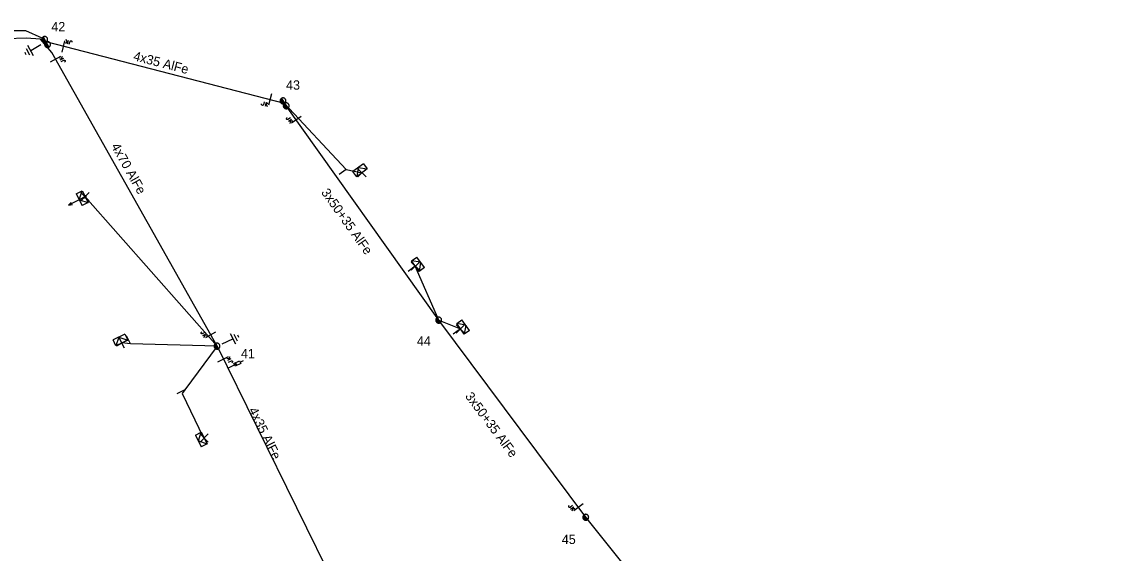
# Model space of a CAD drawing. Extents: x -536149 to -535465, y -1201639 to -1201298.
# Drawn here: x -535725.2 to -535608.3, y -1201357.9 to -1201301.1 of the extents above; entities that cross this region are included whole.
import ezdxf

# ---------------------------------------------------------------- set-up
doc = ezdxf.new("R2010")
doc.units = 0
for name, color, linetype in [('Vrstva 1', 7, 'Continuous'), ('Vrstva 13', 7, 'Continuous'), ('Vrstva 14', 7, 'Continuous'), ('Vrstva 15', 7, 'Continuous'), ('Vrstva 16', 7, 'Continuous'), ('Vrstva 18', 7, 'Continuous'), ('Vrstva 2', 7, 'Continuous'), ('Vrstva 31', 7, 'Continuous'), ('Vrstva 34', 7, 'Continuous'), ('Vrstva 5', 7, 'Continuous'), ('Vrstva 50', 7, 'Continuous'), ('Vrstva 54', 7, 'Continuous'), ('Vrstva 8', 7, 'Continuous'), ('Vrstva 9', 7, 'Continuous')]:
    doc.layers.add(name, color=color, linetype=linetype)

# ---------------------------------------------------------------- blocks, each defined once
blk = doc.blocks.new('NN440')
at = {"layer": 'Vrstva 2'}
for points in [[(0.63, 0), (0.63, 0.06), (0.62, 0.13), (0.6, 0.19), (0.58, 0.25), (0.55, 0.31), (0.51, 0.37), (0.47, 0.42), (0.42, 0.46), (0.37, 0.51), (0.32, 0.54), (0.26, 0.57), (0.2, 0.59), (0.13, 0.61), (0.07, 0.62), (0, 0.63), (-0.06, 0.62), (-0.13, 0.61), (-0.19, 0.59), (-0.26, 0.57), (-0.31, 0.54), (-0.37, 0.51), (-0.42, 0.46), (-0.47, 0.42), (-0.51, 0.37), (-0.54, 0.31), (-0.57, 0.25), (-0.6, 0.19), (-0.62, 0.13), (-0.63, 0.06), (-0.63, 0), (-0.63, -0.07), (-0.62, -0.14), (-0.6, -0.2), (-0.57, -0.26), (-0.54, -0.32), (-0.51, -0.37), (-0.47, -0.43), (-0.42, -0.47), (-0.37, -0.51), (-0.31, -0.55), (-0.26, -0.58), (-0.19, -0.6), (-0.13, -0.62), (-0.06, -0.63), (0, -0.63), (0.07, -0.63), (0.13, -0.62), (0.2, -0.6), (0.26, -0.58), (0.32, -0.55), (0.37, -0.51), (0.42, -0.47), (0.47, -0.43), (0.51, -0.37), (0.55, -0.32), (0.58, -0.26), (0.6, -0.2), (0.62, -0.14), (0.63, -0.07), (0.63, 0)], [(-0.63, 0), (0.63, 0)], [(-0.6, -0.18), (0.57, -0.18)], [(-0.51, -0.32), (0.5, -0.32)], [(-0.37, -0.47), (0.35, -0.47)]]:
    blk.add_lwpolyline(points, dxfattribs=at)
blk = doc.blocks.new('NN450')
at = {"layer": 'Vrstva 2'}
for points in [[(0, 0), (0, 0.07), (-0.01, 0.13), (-0.03, 0.19), (-0.05, 0.25), (-0.08, 0.31), (-0.12, 0.37), (-0.16, 0.42), (-0.21, 0.46), (-0.26, 0.51), (-0.31, 0.54), (-0.37, 0.57), (-0.43, 0.59), (-0.5, 0.61), (-0.56, 0.62), (-0.63, 0.62), (-0.69, 0.62), (-0.75, 0.61), (-0.82, 0.59), (-0.88, 0.57), (-0.94, 0.54), (-0.99, 0.51), (-1.04, 0.46), (-1.09, 0.42), (-1.13, 0.37), (-1.17, 0.31), (-1.2, 0.25), (-1.22, 0.19), (-1.24, 0.13), (-1.25, 0.07), (-1.25, 0), (-1.25, -0.07), (-1.24, -0.13), (-1.22, -0.19), (-1.2, -0.25), (-1.17, -0.31), (-1.13, -0.37), (-1.09, -0.42), (-1.04, -0.46), (-0.99, -0.51), (-0.94, -0.54), (-0.88, -0.57), (-0.82, -0.59), (-0.75, -0.61), (-0.69, -0.62), (-0.62, -0.63), (-0.56, -0.62), (-0.5, -0.61), (-0.43, -0.59), (-0.37, -0.57), (-0.31, -0.54), (-0.26, -0.51), (-0.21, -0.46), (-0.16, -0.42), (-0.12, -0.37), (-0.08, -0.31), (-0.05, -0.25), (-0.03, -0.19), (-0.01, -0.13), (0, -0.07), (0, 0)], [(1.25, 0), (1.25, 0.07), (1.24, 0.13), (1.22, 0.19), (1.2, 0.25), (1.17, 0.31), (1.13, 0.37), (1.09, 0.42), (1.04, 0.46), (0.99, 0.51), (0.94, 0.54), (0.88, 0.57), (0.82, 0.59), (0.75, 0.61), (0.69, 0.62), (0.62, 0.62), (0.56, 0.62), (0.5, 0.61), (0.43, 0.59), (0.37, 0.57), (0.31, 0.54), (0.26, 0.51), (0.21, 0.46), (0.16, 0.42), (0.12, 0.37), (0.08, 0.31), (0.05, 0.25), (0.03, 0.19), (0.01, 0.13), (0, 0.07), (0, 0), (0, -0.07), (0.01, -0.13), (0.03, -0.19), (0.05, -0.25), (0.08, -0.31), (0.12, -0.37), (0.16, -0.42), (0.21, -0.46), (0.26, -0.51), (0.31, -0.54), (0.37, -0.57), (0.43, -0.59), (0.5, -0.61), (0.56, -0.62), (0.63, -0.63), (0.69, -0.62), (0.75, -0.61), (0.82, -0.59), (0.88, -0.57), (0.94, -0.54), (0.99, -0.51), (1.04, -0.46), (1.09, -0.42), (1.13, -0.37), (1.17, -0.31), (1.2, -0.25), (1.22, -0.19), (1.24, -0.13), (1.25, -0.07), (1.25, 0)], [(-1.25, 0), (1.25, 0)], [(-1.23, -0.16), (-0.02, -0.16)], [(-1.16, -0.32), (-0.09, -0.32)], [(-1.03, -0.47), (-0.22, -0.47)], [(0.02, -0.16), (1.23, -0.16)], [(0.09, -0.32), (1.16, -0.32)], [(0.22, -0.47), (1.03, -0.47)]]:
    blk.add_lwpolyline(points, dxfattribs=at)
blk = doc.blocks.new('NN560')
at = {"layer": 'Vrstva 2'}
for points in [[(2, 0), (1.59, 0.14)], [(0, 0), (2, 0)], [(2, 0), (1.59, -0.13)]]:
    blk.add_lwpolyline(points, dxfattribs=at)
blk = doc.blocks.new('NN840')
at = {"layer": 'Vrstva 15'}
for points in [[(0, 0.62), (0, -0.63)], [(-0.75, -0.71), (-0.75, -0.66)], [(-0.73, -0.76), (-0.75, -0.71)], [(-0.66, -0.8), (-0.73, -0.76)], [(-0.63, -0.8), (-0.66, -0.8)], [(-0.56, -0.76), (-0.63, -0.8)], [(-0.54, -0.71), (-0.56, -0.76)], [(-0.54, -0.38), (-0.54, -0.71)], [(-0.33, -0.38), (-0.33, -0.8)], [(-0.33, -0.64), (-0.13, -0.38)], [(-0.26, -0.56), (-0.09, -0.8)]]:
    blk.add_lwpolyline(points, dxfattribs=at)
blk = doc.blocks.new('NN800')
at = {"layer": 'Vrstva 1'}
for points in [[(-0.44, 0.44), (0.44, -0.44)], [(-0.44, -0.44), (0.44, 0.44)]]:
    blk.add_lwpolyline(points, dxfattribs=at)
blk = doc.blocks.new('NN820')
at = {"layer": 'Vrstva 13'}
for points in [[(0, 0), (0, -1.05)], [(-0.16, -0.81), (0.16, -0.81)], [(-0.16, -1.47), (-0.16, -0.81)], [(0, -1.05), (-0.06, -0.93)], [(0, -1.05), (0.06, -0.93)], [(0.16, -0.81), (0.16, -1.47)], [(0.16, -1.47), (-0.16, -1.47)], [(0, -1.47), (0, -1.87)]]:
    blk.add_lwpolyline(points, dxfattribs=at)
blk = doc.blocks.new('NN630')
at = {"layer": 'Vrstva 9'}
for points in [[(0, -0.7), (-0.7, 0)], [(-0.7, -0.7), (-0.7, 0), (0.7, 0), (0.7, -0.7)], [(-0.7, -0.7), (0.7, -0.7)], [(0, -0.7), (0.7, 0)]]:
    blk.add_lwpolyline(points, dxfattribs=at)
blk = doc.blocks.new('NN810')
at = {"layer": 'Vrstva 14'}
for points in [[(0, -0.64), (0, -1.89)], [(0.63, -1.89), (-0.62, -1.89)], [(0.39, -2.2), (-0.4, -2.2)], [(0, -2.52), (-0.12, -2.52)], [(0.14, -2.52), (0, -2.52)]]:
    blk.add_lwpolyline(points, dxfattribs=at)
blk = doc.blocks.new('NN500')
at = {"layer": 'Vrstva 2'}
for points in [[(0, -0.24), (0.02, -0.23), (0.05, -0.23), (0.07, -0.22), (0.09, -0.22), (0.12, -0.2), (0.14, -0.19), (0.16, -0.18), (0.17, -0.16), (0.19, -0.14), (0.2, -0.12), (0.21, -0.1), (0.22, -0.07), (0.23, -0.05), (0.23, -0.02), (0.23, 0), (0.23, 0.02), (0.23, 0.05), (0.22, 0.07), (0.21, 0.1), (0.2, 0.12), (0.19, 0.14), (0.17, 0.16), (0.16, 0.17), (0.14, 0.19), (0.12, 0.2), (0.09, 0.21), (0.07, 0.22), (0.05, 0.23), (0.02, 0.23), (0, 0.23), (-0.03, 0.23), (-0.05, 0.23), (-0.07, 0.22), (-0.1, 0.21), (-0.12, 0.2), (-0.14, 0.19), (-0.16, 0.17), (-0.18, 0.16), (-0.19, 0.14), (-0.2, 0.12), (-0.22, 0.1), (-0.22, 0.07), (-0.23, 0.05), (-0.23, 0.02), (-0.24, 0), (-0.23, -0.02), (-0.23, -0.05), (-0.22, -0.07), (-0.22, -0.1), (-0.2, -0.12), (-0.19, -0.14), (-0.18, -0.16), (-0.16, -0.18), (-0.14, -0.19), (-0.12, -0.2), (-0.1, -0.22), (-0.07, -0.22), (-0.05, -0.23), (-0.03, -0.23), (0, -0.24)], [(0, -0.24), (0.02, -0.23), (0.05, -0.23), (0.07, -0.22), (0.09, -0.22), (0.12, -0.2), (0.14, -0.19), (0.16, -0.18), (0.17, -0.16), (0.19, -0.14), (0.2, -0.12), (0.21, -0.1), (0.22, -0.07), (0.23, -0.05), (0.23, -0.02), (0.23, 0), (0.23, 0.02), (0.23, 0.05), (0.22, 0.07), (0.21, 0.1), (0.2, 0.12), (0.19, 0.14), (0.17, 0.16), (0.16, 0.17), (0.14, 0.19), (0.12, 0.2), (0.09, 0.21), (0.07, 0.22), (0.05, 0.23), (0.02, 0.23), (0, 0.23), (-0.03, 0.23), (-0.05, 0.23), (-0.07, 0.22), (-0.1, 0.21), (-0.12, 0.2), (-0.14, 0.19), (-0.16, 0.17), (-0.18, 0.16), (-0.19, 0.14), (-0.2, 0.12), (-0.22, 0.1), (-0.22, 0.07), (-0.23, 0.05), (-0.23, 0.02), (-0.24, 0), (-0.23, -0.02), (-0.23, -0.05), (-0.22, -0.07), (-0.22, -0.1), (-0.2, -0.12), (-0.19, -0.14), (-0.18, -0.16), (-0.16, -0.18), (-0.14, -0.19), (-0.12, -0.2), (-0.1, -0.22), (-0.07, -0.22), (-0.05, -0.23), (-0.03, -0.23), (0, -0.24)], [(0, -0.21), (0.02, -0.2), (0.04, -0.2), (0.06, -0.2), (0.08, -0.19), (0.1, -0.18), (0.12, -0.17), (0.14, -0.15), (0.15, -0.14), (0.16, -0.12), (0.18, -0.1), (0.19, -0.08), (0.19, -0.06), (0.2, -0.04), (0.2, -0.02), (0.2, 0), (0.2, 0.02), (0.2, 0.04), (0.19, 0.06), (0.19, 0.08), (0.18, 0.1), (0.16, 0.12), (0.15, 0.14), (0.14, 0.15), (0.12, 0.17), (0.1, 0.18), (0.08, 0.19), (0.06, 0.19), (0.04, 0.2), (0.02, 0.2), (0, 0.2), (-0.02, 0.2), (-0.04, 0.2), (-0.06, 0.19), (-0.08, 0.19), (-0.1, 0.18), (-0.12, 0.17), (-0.14, 0.15), (-0.15, 0.14), (-0.17, 0.12), (-0.18, 0.1), (-0.19, 0.08), (-0.2, 0.06), (-0.2, 0.04), (-0.21, 0.02), (-0.21, 0), (-0.21, -0.02), (-0.2, -0.04), (-0.2, -0.06), (-0.19, -0.08), (-0.18, -0.1), (-0.17, -0.12), (-0.15, -0.14), (-0.14, -0.15), (-0.12, -0.17), (-0.1, -0.18), (-0.08, -0.19), (-0.06, -0.2), (-0.04, -0.2), (-0.02, -0.2), (0, -0.21)], [(0, -0.18), (0.02, -0.18), (0.04, -0.17), (0.05, -0.17), (0.07, -0.16), (0.09, -0.15), (0.1, -0.14), (0.12, -0.13), (0.13, -0.12), (0.14, -0.1), (0.15, -0.09), (0.16, -0.07), (0.17, -0.05), (0.17, -0.04), (0.17, -0.02), (0.17, 0), (0.17, 0.02), (0.17, 0.04), (0.17, 0.05), (0.16, 0.07), (0.15, 0.09), (0.14, 0.1), (0.13, 0.12), (0.12, 0.13), (0.1, 0.14), (0.09, 0.15), (0.07, 0.16), (0.05, 0.17), (0.04, 0.17), (0.02, 0.17), (0, 0.18), (-0.02, 0.17), (-0.04, 0.17), (-0.06, 0.17), (-0.07, 0.16), (-0.09, 0.15), (-0.1, 0.14), (-0.12, 0.13), (-0.13, 0.12), (-0.14, 0.1), (-0.15, 0.09), (-0.16, 0.07), (-0.17, 0.05), (-0.17, 0.04), (-0.18, 0.02), (-0.18, 0), (-0.18, -0.02), (-0.17, -0.04), (-0.17, -0.05), (-0.16, -0.07), (-0.15, -0.09), (-0.14, -0.1), (-0.13, -0.12), (-0.12, -0.13), (-0.1, -0.14), (-0.09, -0.15), (-0.07, -0.16), (-0.06, -0.17), (-0.04, -0.17), (-0.02, -0.18), (0, -0.18)], [(0, -0.15), (0.01, -0.15), (0.03, -0.14), (0.04, -0.14), (0.06, -0.13), (0.07, -0.13), (0.08, -0.12), (0.1, -0.11), (0.11, -0.1), (0.12, -0.09), (0.13, -0.07), (0.13, -0.06), (0.14, -0.05), (0.14, -0.03), (0.14, -0.02), (0.14, 0), (0.14, 0.01), (0.14, 0.03), (0.14, 0.04), (0.13, 0.06), (0.13, 0.07), (0.12, 0.09), (0.11, 0.1), (0.1, 0.11), (0.08, 0.12), (0.07, 0.13), (0.06, 0.13), (0.04, 0.14), (0.03, 0.14), (0.01, 0.14), (0, 0.15), (-0.02, 0.14), (-0.03, 0.14), (-0.05, 0.14), (-0.06, 0.13), (-0.07, 0.13), (-0.09, 0.12), (-0.1, 0.11), (-0.11, 0.1), (-0.12, 0.09), (-0.13, 0.07), (-0.13, 0.06), (-0.14, 0.04), (-0.14, 0.03), (-0.15, 0.01), (-0.15, 0), (-0.15, -0.02), (-0.14, -0.03), (-0.14, -0.05), (-0.13, -0.06), (-0.13, -0.07), (-0.12, -0.09), (-0.11, -0.1), (-0.1, -0.11), (-0.09, -0.12), (-0.07, -0.13), (-0.06, -0.13), (-0.05, -0.14), (-0.03, -0.14), (-0.02, -0.15), (0, -0.15)], [(0, -0.12), (0.01, -0.12), (0.02, -0.11), (0.03, -0.11), (0.05, -0.11), (0.06, -0.1), (0.07, -0.09), (0.08, -0.09), (0.09, -0.08), (0.09, -0.07), (0.1, -0.06), (0.11, -0.05), (0.11, -0.04), (0.11, -0.02), (0.11, -0.01), (0.12, 0), (0.11, 0.01), (0.11, 0.02), (0.11, 0.04), (0.11, 0.05), (0.1, 0.06), (0.09, 0.07), (0.09, 0.08), (0.08, 0.09), (0.07, 0.09), (0.06, 0.1), (0.05, 0.11), (0.03, 0.11), (0.02, 0.11), (0.01, 0.12), (0, 0.12), (-0.01, 0.12), (-0.03, 0.11), (-0.04, 0.11), (-0.05, 0.11), (-0.06, 0.1), (-0.07, 0.09), (-0.08, 0.09), (-0.09, 0.08), (-0.1, 0.07), (-0.1, 0.06), (-0.11, 0.05), (-0.11, 0.04), (-0.12, 0.02), (-0.12, 0.01), (-0.12, 0), (-0.12, -0.01), (-0.12, -0.02), (-0.11, -0.04), (-0.11, -0.05), (-0.1, -0.06), (-0.1, -0.07), (-0.09, -0.08), (-0.08, -0.09), (-0.07, -0.09), (-0.06, -0.1), (-0.05, -0.11), (-0.04, -0.11), (-0.03, -0.11), (-0.01, -0.12), (0, -0.12)], [(0, -0.09), (0.01, -0.09), (0.02, -0.09), (0.03, -0.08), (0.03, -0.08), (0.04, -0.08), (0.05, -0.07), (0.06, -0.07), (0.06, -0.06), (0.07, -0.05), (0.07, -0.04), (0.08, -0.04), (0.08, -0.03), (0.08, -0.02), (0.09, -0.01), (0.09, 0), (0.09, 0.01), (0.08, 0.02), (0.08, 0.03), (0.08, 0.03), (0.07, 0.04), (0.07, 0.05), (0.06, 0.06), (0.06, 0.06), (0.05, 0.07), (0.04, 0.07), (0.03, 0.08), (0.03, 0.08), (0.02, 0.08), (0.01, 0.09), (0, 0.09), (-0.01, 0.09), (-0.02, 0.08), (-0.03, 0.08), (-0.04, 0.08), (-0.04, 0.07), (-0.05, 0.07), (-0.06, 0.06), (-0.07, 0.06), (-0.07, 0.05), (-0.08, 0.04), (-0.08, 0.03), (-0.08, 0.03), (-0.09, 0.02), (-0.09, 0.01), (-0.09, 0), (-0.09, -0.01), (-0.09, -0.02), (-0.08, -0.03), (-0.08, -0.04), (-0.08, -0.04), (-0.07, -0.05), (-0.07, -0.06), (-0.06, -0.07), (-0.05, -0.07), (-0.04, -0.08), (-0.04, -0.08), (-0.03, -0.08), (-0.02, -0.09), (-0.01, -0.09), (0, -0.09)], [(0, -0.06), (0, -0.06), (0.01, -0.06), (0.02, -0.05), (0.02, -0.05), (0.03, -0.05), (0.03, -0.05), (0.04, -0.04), (0.04, -0.04), (0.05, -0.03), (0.05, -0.03), (0.05, -0.02), (0.05, -0.02), (0.05, -0.01), (0.06, -0.01), (0.06, 0), (0.06, 0.01), (0.05, 0.01), (0.05, 0.02), (0.05, 0.02), (0.05, 0.03), (0.05, 0.03), (0.04, 0.04), (0.04, 0.04), (0.03, 0.05), (0.03, 0.05), (0.02, 0.05), (0.02, 0.05), (0.01, 0.06), (0, 0.06), (0, 0.06), (-0.01, 0.06), (-0.01, 0.06), (-0.02, 0.05), (-0.02, 0.05), (-0.03, 0.05), (-0.03, 0.05), (-0.04, 0.04), (-0.04, 0.04), (-0.05, 0.03), (-0.05, 0.03), (-0.05, 0.02), (-0.06, 0.02), (-0.06, 0.01), (-0.06, 0.01), (-0.06, 0), (-0.06, -0.01), (-0.06, -0.01), (-0.06, -0.02), (-0.05, -0.02), (-0.05, -0.03), (-0.05, -0.03), (-0.04, -0.04), (-0.04, -0.04), (-0.03, -0.05), (-0.03, -0.05), (-0.02, -0.05), (-0.02, -0.05), (-0.01, -0.06), (-0.01, -0.06), (0, -0.06)], [(0, -0.03), (0, -0.03), (0, -0.03), (0.01, -0.03), (0.01, -0.03), (0.01, -0.02), (0.02, -0.02), (0.02, -0.02), (0.02, -0.02), (0.02, -0.02), (0.02, -0.01), (0.02, -0.01), (0.03, -0.01), (0.03, -0.01), (0.03, 0), (0.03, 0), (0.03, 0), (0.03, 0.01), (0.03, 0.01), (0.02, 0.01), (0.02, 0.01), (0.02, 0.02), (0.02, 0.02), (0.02, 0.02), (0.02, 0.02), (0.01, 0.02), (0.01, 0.02), (0.01, 0.03), (0, 0.03), (0, 0.03), (0, 0.03), (0, 0.03), (-0.01, 0.03), (-0.01, 0.03), (-0.01, 0.02), (-0.02, 0.02), (-0.02, 0.02), (-0.02, 0.02), (-0.02, 0.02), (-0.02, 0.02), (-0.03, 0.01), (-0.03, 0.01), (-0.03, 0.01), (-0.03, 0.01), (-0.03, 0), (-0.03, 0), (-0.03, 0), (-0.03, -0.01), (-0.03, -0.01), (-0.03, -0.01), (-0.03, -0.01), (-0.02, -0.02), (-0.02, -0.02), (-0.02, -0.02), (-0.02, -0.02), (-0.02, -0.02), (-0.01, -0.03), (-0.01, -0.03), (-0.01, -0.03), (0, -0.03), (0, -0.03)], [(0.23, 0), (0.7, 0)]]:
    blk.add_lwpolyline(points, dxfattribs=at)
blk = doc.blocks.new('NN510')
at = {"layer": 'Vrstva 2'}
blk.add_lwpolyline([(0, 0), (0, 0.94)], dxfattribs=at)

msp = doc.modelspace()

# ---------------------------------------------------------------- linework, layer by layer
at = {"layer": 'Vrstva 1'}
for points in [[(-535697.05, -1201309.82), (-535722.56, -1201303.26)], [(-535704.28, -1201335.78), (-535721.94, -1201304.37)], [(-535664.84, -1201354.08), (-535680.57, -1201333), (-535697.05, -1201309.82)], [(-535704.28, -1201335.78), (-535687.29, -1201370.27), (-535663.05, -1201399.63), (-535635.32, -1201433.41), (-535614.86, -1201457.77), (-535589.24, -1201487.74), (-535570.26, -1201520.7), (-535562.05, -1201543.24)]]:
    msp.add_lwpolyline(points, dxfattribs=at)
at = {"layer": 'Vrstva 5'}
for points in [[(-535722.56, -1201303.26), (-535722.98, -1201302.84), (-535724.72, -1201302.08), (-535727.05, -1201302.08), (-535730.58, -1201303.91), (-535729.84, -1201305.91), (-535729.81, -1201305.99)], [(-535721.94, -1201304.37), (-535723.15, -1201302.96), (-535724.7, -1201302.86), (-535726.8, -1201302.91), (-535729.94, -1201304.32), (-535729.71, -1201305.86), (-535729.68, -1201305.94)]]:
    msp.add_lwpolyline(points, dxfattribs=at)
at = {"layer": 'Vrstva 50'}
msp.add_lwpolyline([(-535627.8, -1201404.56), (-535635.71, -1201393.75), (-535645.04, -1201380.87), (-535652.14, -1201371.01), (-535656.06, -1201365.68), (-535659.69, -1201360.49), (-535664.84, -1201354.08), (-535664.84, -1201354.08)], dxfattribs=at)
at = {"layer": 'Vrstva 54'}
for points in [[(-535697.05, -1201309.82), (-535690.48, -1201316.88), (-535688.77, -1201317.25)], [(-535704.28, -1201335.78), (-535718.39, -1201319.81)], [(-535680.57, -1201333), (-535683.07, -1201327.23)], [(-535680.57, -1201333), (-535678.25, -1201333.94)]]:
    msp.add_lwpolyline(points, dxfattribs=at)
at = {"layer": 'Vrstva 8'}
for points in [[(-535704.28, -1201335.78), (-535713.54, -1201335.53), (-535714.46, -1201335.44)], [(-535704.28, -1201335.78), (-535707.73, -1201340.47), (-535708.02, -1201340.86), (-535705.77, -1201345.51), (-535705.65, -1201345.61)]]:
    msp.add_lwpolyline(points, dxfattribs=at)

# ---------------------------------------------------------------- block references
at = {"layer": 'Vrstva 13'}
for name, p, xscale, yscale, rotation in [('NN450', (-535722.56, -1201303.26), 0.5000000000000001, 0.5, -60.70329164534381), ('NN450', (-535697.05, -1201309.82), 0.5, 0.5, -56.92560833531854), ('NN500', (-535718.39, -1201319.81), 0.49999999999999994, 0.5, -153.23499995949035), ('NN440', (-535680.57, -1201333), 0.5, 0.5000000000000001, -53.27259439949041), ('NN440', (-535704.28, -1201335.78), 0.5000000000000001, 0.5, -63.8193083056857), ('NN440', (-535664.84, -1201354.08), 0.49999999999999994, 0.5000000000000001, -51.207491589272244)]:
    msp.add_blockref(name, p, dxfattribs=dict(at, xscale=xscale, yscale=yscale, rotation=rotation))
for name, p, rotation in [('NN510', (-535690.47, -1201316.88), 126.12148895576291), ('NN560', (-535718.39, -1201319.81), -153.27410561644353), ('NN510', (-535683.07, -1201327.23), 126.2071916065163), ('NN510', (-535678.24, -1201333.94), 125.6026861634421), ('NN510', (-535713.54, -1201335.53), 26.25728886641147), ('NN510', (-535707.73, -1201340.47), 116.07314170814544)]:
    msp.add_blockref(name, p, dxfattribs=dict(at, rotation=rotation))
at = {"layer": 'Vrstva 15'}
for p, rotation in [((-535722.56, -1201303.26), -60.57565824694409), ((-535704.29, -1201335.8), 115.58682774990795)]:
    msp.add_blockref('NN810', p, dxfattribs=dict(at, rotation=rotation))
at = {"layer": 'Vrstva 16', "rotation": 116.25315000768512}
msp.add_blockref('NN820', (-535703.14, -1201338.14), dxfattribs=at)
at = {"layer": 'Vrstva 18'}
for p, rotation in [((-535720.7, -1201303.74), 165.55157766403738), ((-535721.54, -1201305.08), 119.4915888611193), ((-535698.62, -1201309.42), -14.41305004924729), ((-535695.8, -1201311.58), -54.55930825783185), ((-535704.97, -1201334.59), -60.572613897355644), ((-535703.62, -1201337.17), 116.22331942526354), ((-535665.62, -1201353.03), -53.27303885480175)]:
    msp.add_blockref('NN840', p, dxfattribs=dict(at, rotation=rotation))
at = {"layer": 'Vrstva 31'}
for p, rotation in [((-535688.77, -1201317.25), -143.8311750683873), ((-535718.39, -1201319.81), -63.27828332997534), ((-535683.07, -1201327.23), 126.21445003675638), ((-535678.24, -1201333.94), 125.58795275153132), ((-535714.46, -1201335.44), -153.7736972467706), ((-535705.65, -1201345.61), -63.849822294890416)]:
    msp.add_blockref('NN630', p, dxfattribs=dict(at, rotation=rotation))
at = {"layer": 'Vrstva 34'}
for p in [(-535688.77, -1201317.25), (-535718.39, -1201319.81), (-535683.07, -1201327.23), (-535678.25, -1201333.94), (-535705.65, -1201345.61)]:
    msp.add_blockref('NN800', p, dxfattribs=at)
at = {"layer": 'Vrstva 34', "rotation": 73.12296663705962}
msp.add_blockref('NN800', (-535714.46, -1201335.44), dxfattribs=at)

# ---------------------------------------------------------------- texts
at = {"layer": 'Vrstva 14'}
for s, p in [('42', (-535722, -1201302.12)), ('43', (-535696.89, -1201308.36)), ('44', (-535682.9, -1201335.73)), ('41', (-535701.72, -1201337.08)), ('45', (-535667.4, -1201356.94))]:
    msp.add_text(s, height=1, dxfattribs=at).set_placement(p)
at = {"layer": 'Vrstva 2'}
for s, rotation, p in [('4x35 AlFe', 345.579, (-535713.3, -1201305.2)), ('4x70 AlFe', 299.349, (-535715.64, -1201314.4)), ('3x50+35 AlFe', 305.415, (-535693.19, -1201319.35)), ('3x50+35 AlFe', 306.727, (-535677.8, -1201341.15)), ('4x35 AlFe', 296.225, (-535700.94, -1201342.62))]:
    msp.add_text(s, height=1, rotation=rotation, dxfattribs=at).set_placement(p)

doc.saveas('drawing.dxf')
